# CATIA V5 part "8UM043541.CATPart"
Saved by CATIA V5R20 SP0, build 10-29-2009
Part number: 8UM043541
Revision: ANY
Definition: UNKNOWN
Nomenclature: 8UM043541
Source: Unknown
Bounding box of the stored display mesh (mm): x -35 to 0, y 0 to 41, z 0 to 3.8
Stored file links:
  C:\Users\Utente\Desktop\IO LAVORO\3D X SITO CF\X SITO\3D files UM\UM043642 PRODUCT\8UM043541.CATPart
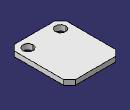
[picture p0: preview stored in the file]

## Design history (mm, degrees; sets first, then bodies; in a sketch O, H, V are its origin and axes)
Body1 "Chaflán3" (main body)
  Solid1: solid without history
